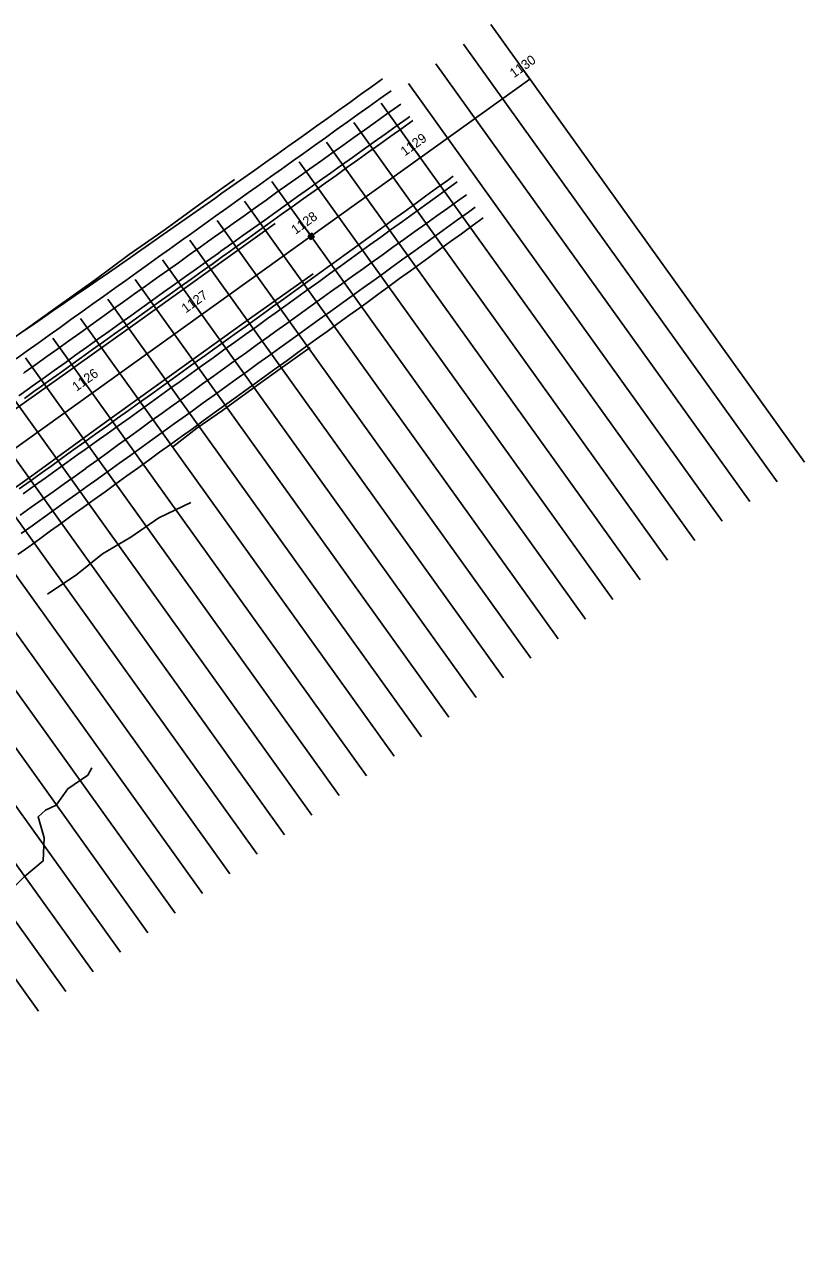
# Model space of a CAD drawing. Extents: x -354 to 8821, y -19535 to 19639.
# Drawn here: x 8242 to 8821, y 1707 to 2622 of the extents above; entities that cross this region are included whole.
import ezdxf

# ---------------------------------------------------------------- set-up
doc = ezdxf.new("R2010")
doc.units = 0
for name, color, linetype in [('DR_X_Cells', 7, 'Continuous'), ('GK_Drainage_Nodes', 7, 'Continuous'), ('PV_X_COP', 7, 'Continuous'), ('PV_X_EOP', 7, 'Continuous'), ('PV_X_Shoulder_Aggregate', 7, 'Continuous'), ('RW_X_CL_50', 7, 'Continuous'), ('SC_Scratch1', 7, 'Continuous'), ('SV_X_Edge_of_Slip', 7, 'Continuous'), ('SV_X_Top_of_Bank', 7, 'Continuous')]:
    doc.layers.add(name, color=color, linetype=linetype)

msp = doc.modelspace()

# ---------------------------------------------------------------- linework, layer by layer
at = {"layer": 'DR_X_Cells'}
for p, q in [((8453.29, 2464.24), (8453.48, 2465.1)), ((8453.9, 2463.28), (8454.43, 2465.71)), ((8454.69, 2463.16), (8455.2, 2465.5)), ((8455.65, 2463.77), (8455.81, 2464.55))]:
    msp.add_line(p, q, dxfattribs=at)
for points in [[(8452.23, 2464.92), (8455.04, 2466.72), (8456.84, 2463.92), (8454.03, 2462.12)], [(8452.95, 2464.76), (8454.88, 2466), (8456.12, 2464.07), (8454.19, 2462.84)], [(8453.15, 2464.72), (8454.84, 2465.8), (8455.92, 2464.12), (8454.23, 2463.04)]]:
    msp.add_lwpolyline(points, close=True, dxfattribs=at)
at = {"layer": 'GK_Drainage_Nodes'}
for p, q in [((8453.63, 2465.82), (8453.63, 2465.82)), ((8453.69, 2463.88), (8453.69, 2463.88)), ((8453.99, 2465.26), (8453.99, 2465.26)), ((8454.54, 2464.42), (8454.54, 2464.42)), ((8454.54, 2464.42), (8454.54, 2464.42)), ((8454.54, 2464.42), (8454.54, 2464.42)), ((8455.08, 2463.58), (8455.08, 2463.58)), ((8455.38, 2464.96), (8455.38, 2464.96)), ((8455.44, 2463.02), (8455.44, 2463.02))]:
    msp.add_line(p, q, dxfattribs=at)
at = {"layer": 'PV_X_COP'}
for points in [[(8240.75, 2362.63), (8241.93, 2363.47), (8250.06, 2369.29), (8258.19, 2375.11), (8266.33, 2380.93), (8274.46, 2386.74), (8282.6, 2392.56), (8290.73, 2398.37), (8298.87, 2404.19), (8307.01, 2410), (8315.14, 2415.81), (8323.28, 2421.63), (8331.42, 2427.44), (8339.56, 2433.25), (8347.69, 2439.06), (8355.83, 2444.87), (8363.97, 2450.68), (8372.11, 2456.49), (8380.25, 2462.3), (8388.39, 2468.11), (8396.53, 2473.91), (8404.67, 2479.72), (8412.82, 2485.53), (8420.96, 2491.33), (8429.1, 2497.14), (8437.24, 2502.94), (8445.39, 2508.75), (8453.53, 2514.55), (8461.67, 2520.35), (8469.82, 2526.16), (8477.96, 2531.96), (8486.11, 2537.76), (8494.26, 2543.56), (8502.4, 2549.36), (8510.55, 2555.16), (8518.69, 2560.96), (8521.05, 2562.63)], [(8246.57, 2263.13), (8254.71, 2268.94), (8262.85, 2274.75), (8270.99, 2280.56), (8279.13, 2286.37), (8287.1, 2292.05), (8287.1, 2292.05), (8287.11, 2292.06), (8287.13, 2292.08), (8287.15, 2292.09), (8287.17, 2292.1), (8287.17, 2292.1), (8295.26, 2297.97), (8303.36, 2303.83), (8311.46, 2309.7), (8319.57, 2315.56), (8327.67, 2321.42), (8335.77, 2327.28), (8343.88, 2333.13), (8351.99, 2338.99), (8357.68, 2343.1), (8365.79, 2348.95), (8373.9, 2354.8), (8382.01, 2360.65), (8390.13, 2366.5), (8398.24, 2372.34), (8406.36, 2378.18), (8414.47, 2384.02), (8422.59, 2389.86), (8428.29, 2393.96), (8436.42, 2399.8), (8444.54, 2405.63), (8452.66, 2411.46), (8460.78, 2417.3), (8468.91, 2423.12), (8477.04, 2428.95), (8485.17, 2434.78), (8493.3, 2440.6), (8499.01, 2444.69), (8507.14, 2450.51), (8515.27, 2456.33), (8523.41, 2462.14), (8531.54, 2467.96), (8539.68, 2473.77), (8547.82, 2479.58), (8555.96, 2485.39), (8564.1, 2491.2), (8569.82, 2495.28)], [(8238.44, 2257.32), (8246.57, 2263.13)]]:
    msp.add_lwpolyline(points, dxfattribs=at)
at = {"layer": 'PV_X_EOP'}
for points in [[(8513.88, 2572.53), (8505.74, 2566.73), (8497.6, 2560.92), (8489.46, 2555.11), (8481.32, 2549.3), (8473.18, 2543.49), (8465.04, 2537.68), (8456.9, 2531.87), (8448.76, 2526.06), (8440.62, 2520.25), (8432.48, 2514.44), (8424.35, 2508.63), (8416.21, 2502.82), (8408.07, 2497.01), (8399.93, 2491.19), (8391.8, 2485.38), (8383.66, 2479.57), (8375.53, 2473.75), (8373.69, 2472.44), (8365.56, 2466.63), (8357.42, 2460.81), (8349.29, 2455), (8341.15, 2449.18), (8333.02, 2443.37), (8324.88, 2437.55), (8316.75, 2431.73), (8308.62, 2425.91), (8300.48, 2420.09), (8292.35, 2414.28), (8284.22, 2408.46), (8276.08, 2402.64), (8267.95, 2396.82), (8259.82, 2391), (8251.69, 2385.18), (8243.56, 2379.35), (8235.43, 2373.53)], [(8237.26, 2345.92), (8245.39, 2351.74), (8247.28, 2353.09), (8255.41, 2358.91), (8263.54, 2364.73), (8271.67, 2370.55), (8279.8, 2376.37), (8287.94, 2382.19), (8296.07, 2388.01), (8304.2, 2393.82), (8312.34, 2399.64), (8320.47, 2405.46), (8328.61, 2411.27), (8336.74, 2417.09), (8344.88, 2422.9), (8353.01, 2428.72), (8361.15, 2434.53), (8369.28, 2440.35), (8377.42, 2446.16), (8385.56, 2451.97), (8387.45, 2453.32), (8395.59, 2459.14), (8403.72, 2464.95), (8411.86, 2470.76), (8420, 2476.57), (8428.14, 2482.38), (8436.28, 2488.19), (8444.42, 2494), (8452.56, 2499.81), (8460.7, 2505.62), (8468.84, 2511.43), (8476.98, 2517.23), (8485.12, 2523.04), (8493.26, 2528.85), (8501.4, 2534.65), (8509.55, 2540.46), (8517.69, 2546.26), (8525.83, 2552.07), (8527.72, 2553.42)], [(8562.88, 2504.86), (8554.77, 2499), (8546.67, 2493.15), (8538.56, 2487.29), (8530.46, 2481.43), (8522.35, 2475.58), (8514.24, 2469.73), (8506.13, 2463.87), (8498.02, 2458.02), (8492.56, 2454.08), (8484.45, 2448.23), (8476.34, 2442.38), (8468.22, 2436.54), (8460.11, 2430.69), (8452, 2424.84), (8443.88, 2419), (8435.77, 2413.16), (8427.65, 2407.32), (8422.18, 2403.38), (8414.06, 2397.54), (8405.94, 2391.7), (8397.82, 2385.87), (8389.7, 2380.03), (8381.58, 2374.2), (8373.46, 2368.36), (8365.34, 2362.53), (8357.21, 2356.7), (8351.74, 2352.77), (8343.61, 2346.94), (8335.49, 2341.11), (8327.36, 2335.29), (8319.23, 2329.46), (8311.11, 2323.64), (8302.98, 2317.81), (8294.85, 2311.99), (8286.72, 2306.17), (8281.24, 2302.25), (8281.24, 2302.25), (8273.1, 2296.43), (8264.97, 2290.61), (8256.84, 2284.79), (8248.71, 2278.97), (8240.58, 2273.15)], [(8239.06, 2243.6), (8247.19, 2249.42), (8255.33, 2255.24), (8263.46, 2261.07), (8271.59, 2266.89), (8279.72, 2272.71), (8287.85, 2278.53), (8295.98, 2284.35), (8296.14, 2284.47), (8296.14, 2284.47), (8296.14, 2284.47), (8296.15, 2284.48), (8296.16, 2284.48), (8296.17, 2284.49), (8296.17, 2284.49), (8304.29, 2290.32), (8312.41, 2296.16), (8320.53, 2301.99), (8328.65, 2307.83), (8336.77, 2313.67), (8344.89, 2319.5), (8353.01, 2325.34), (8361.13, 2331.18), (8366.26, 2334.86), (8374.38, 2340.7), (8382.5, 2346.54), (8390.62, 2352.38), (8398.74, 2358.22), (8406.85, 2364.05), (8414.97, 2369.89), (8423.09, 2375.73), (8431.21, 2381.57), (8436.34, 2385.26), (8444.45, 2391.1), (8452.57, 2396.94), (8460.69, 2402.79), (8468.8, 2408.63), (8476.92, 2414.47), (8485.03, 2420.31), (8493.15, 2426.15), (8501.27, 2432), (8506.39, 2435.69), (8514.51, 2441.53), (8522.62, 2447.38), (8530.74, 2453.22), (8538.85, 2459.06), (8546.97, 2464.91), (8555.08, 2470.75), (8563.19, 2476.6), (8571.31, 2482.45), (8576.43, 2486.14)]]:
    msp.add_lwpolyline(points, dxfattribs=at)
at = {"layer": 'PV_X_Shoulder_Aggregate'}
for points in [[(8507.45, 2581.41), (8499.34, 2575.57), (8491.22, 2569.73), (8483.1, 2563.89), (8474.98, 2558.06), (8466.85, 2552.24), (8458.71, 2546.42), (8450.57, 2540.61), (8445.31, 2536.86), (8437.17, 2531.06), (8429.02, 2525.27), (8420.86, 2519.48), (8412.7, 2513.7), (8404.54, 2507.92), (8396.37, 2502.15), (8388.2, 2496.39), (8382.92, 2492.67), (8374.74, 2486.92), (8366.56, 2481.17), (8358.37, 2475.43), (8350.18, 2469.69), (8341.98, 2463.97), (8333.78, 2458.24), (8325.58, 2452.53), (8320.28, 2448.84), (8312.07, 2443.13), (8303.85, 2437.43), (8295.63, 2431.74), (8287.4, 2426.05), (8279.18, 2420.37), (8270.94, 2414.69), (8262.7, 2409.02), (8257.38, 2405.36), (8257.38, 2405.36), (8249.15, 2399.69), (8240.92, 2394.01)], [(8529.9, 2550.41), (8521.76, 2544.6), (8513.63, 2538.78), (8505.49, 2532.97), (8497.35, 2527.16), (8489.22, 2521.34), (8481.08, 2515.53), (8472.95, 2509.71), (8464.81, 2503.89), (8456.68, 2498.08), (8448.54, 2492.26), (8440.41, 2486.45), (8432.27, 2480.63), (8424.14, 2474.81), (8416.01, 2468.99), (8407.87, 2463.17), (8399.74, 2457.36), (8391.61, 2451.54), (8389.72, 2450.18), (8381.59, 2444.36), (8373.45, 2438.54), (8365.32, 2432.72), (8357.19, 2426.9), (8349.06, 2421.08), (8340.93, 2415.26), (8332.8, 2409.44), (8324.67, 2403.62), (8316.54, 2397.8), (8308.41, 2391.97), (8300.28, 2386.15), (8292.15, 2380.33), (8284.02, 2374.5), (8275.89, 2368.68), (8267.76, 2362.85), (8259.63, 2357.03), (8251.5, 2351.2), (8249.61, 2349.85), (8241.48, 2344.02)], [(8213.46, 2374.92), (8242.12, 2395.08), (8264.83, 2411.31), (8293.95, 2432.25), (8319.36, 2450.9), (8346.08, 2469.45), (8371.91, 2488.23), (8397.55, 2506.71)], [(8245.76, 2282.64), (8253.89, 2288.47), (8262.01, 2294.3), (8270.14, 2300.13), (8278.26, 2305.96), (8286.38, 2311.79), (8294.51, 2317.62), (8302.63, 2323.45), (8310.76, 2329.28), (8318.88, 2335.12), (8327, 2340.95), (8335.12, 2346.78), (8343.25, 2352.61), (8351.37, 2358.45), (8359.49, 2364.28), (8367.61, 2370.11), (8375.74, 2375.95), (8381.12, 2379.82), (8381.12, 2379.82), (8389.24, 2385.65), (8397.36, 2391.49), (8405.48, 2397.33), (8413.59, 2403.17), (8421.71, 2409.02), (8425.88, 2412.02), (8433.99, 2417.87), (8442.1, 2423.72), (8450.21, 2429.57), (8458.31, 2435.42), (8466.42, 2441.28), (8470.58, 2444.29), (8478.69, 2450.15), (8486.79, 2456.01), (8494.89, 2461.88), (8502.99, 2467.74), (8511.08, 2473.61), (8515.24, 2476.63), (8523.34, 2482.5), (8531.43, 2488.38), (8539.52, 2494.25), (8547.61, 2500.13), (8555.7, 2506.01), (8559.85, 2509.04)], [(8582.18, 2478.19), (8574.11, 2472.29), (8566.04, 2466.4), (8557.96, 2460.5), (8549.88, 2454.61), (8541.8, 2448.71), (8536.39, 2444.78), (8528.31, 2438.89), (8520.23, 2433), (8512.14, 2427.12), (8504.05, 2421.24), (8495.97, 2415.36), (8490.55, 2411.43), (8482.46, 2405.55), (8474.37, 2399.68), (8466.27, 2393.81), (8458.18, 2387.94), (8450.08, 2382.07), (8444.66, 2378.15), (8436.56, 2372.29), (8428.46, 2366.42), (8420.35, 2360.57), (8412.25, 2354.71), (8404.14, 2348.85), (8398.72, 2344.94), (8382.5, 2333.24), (8374.39, 2327.39), (8366.28, 2321.54), (8358.17, 2315.68), (8350.06, 2309.83), (8341.95, 2303.98), (8333.84, 2298.13), (8325.73, 2292.28), (8317.62, 2286.43), (8309.51, 2280.58), (8301.4, 2274.73), (8293.29, 2268.88), (8285.18, 2263.04), (8277.07, 2257.19), (8268.96, 2251.34), (8260.98, 2245.59), (8252.87, 2239.74), (8244.76, 2233.89), (8236.65, 2228.05)], [(8427.82, 2473.88), (8377.92, 2438.43), (8325.47, 2400.65), (8273.79, 2363.79), (8221.55, 2326.85), (8180.8, 2297.81), (8128.12, 2260.38), (8082.15, 2226.78), (8028.58, 2188.39), (7978.98, 2152.72), (7933.92, 2120.35), (7882.32, 2083.22), (7833.79, 2048.53), (7785.45, 2013.27), (7732.67, 1975.86), (7693.88, 1947.56), (7645.37, 1913.17), (7595.97, 1878.05), (7566.01, 1856.18)], [(8455.97, 2436.7), (8404.42, 2400.06), (8350.84, 2361.5), (8300.75, 2325.62), (8248.8, 2287.69), (8207.76, 2258.6), (8155.02, 2221.78), (8108.79, 2189.02), (8054.7, 2149.69), (8004.91, 2114.31), (7957.66, 2080.83), (7908.19, 2045.16), (7859.18, 2009.79), (7810.29, 1974.92), (7758.63, 1937.48), (7720.6, 1910.02), (7671.27, 1875.01), (7622.48, 1839.57), (7594.92, 1820.15)], [(8453.66, 2381.8), (8431.58, 2366.1), (8408.75, 2349.75), (8388.67, 2335.05), (8369.65, 2322.03), (8351.78, 2308.14)], [(8237.64, 2276.81), (8245.76, 2282.64)]]:
    msp.add_lwpolyline(points, dxfattribs=at)
at = {"layer": 'RW_X_CL_50'}
for p, q in [((7397.71, 1707.37), (8616.98, 2581.09)), ((8616.98, 2581.09), (8614.07, 2585.16)), ((8535.69, 2522.84), (8532.78, 2526.91)), ((8454.41, 2464.6), (8451.5, 2468.66)), ((8373.13, 2406.35), (8370.21, 2410.41)), ((8291.84, 2348.1), (8288.93, 2352.16))]:
    msp.add_line(p, q, dxfattribs=at)
at = {"layer": 'SC_Scratch1'}
for p, q in [((8587.85, 2621.73), (8820.85, 2296.6)), ((8567.53, 2607.17), (8800.53, 2282.04)), ((8547.21, 2592.61), (8780.21, 2267.47)), ((8526.89, 2578.05), (8759.88, 2252.91)), ((8506.57, 2563.49), (8739.56, 2238.35)), ((8486.25, 2548.92), (8719.24, 2223.79)), ((8465.93, 2534.36), (8698.92, 2209.22)), ((8445.61, 2519.8), (8678.6, 2194.66)), ((8425.29, 2505.24), (8658.28, 2180.1)), ((8404.96, 2490.68), (8637.96, 2165.54)), ((8384.64, 2476.11), (8617.64, 2150.98)), ((8364.32, 2461.55), (8597.32, 2136.41)), ((8344, 2446.99), (8576.99, 2121.85)), ((8323.68, 2432.43), (8556.67, 2107.29)), ((8303.36, 2417.87), (8536.35, 2092.73)), ((8283.04, 2403.3), (8516.03, 2078.17)), ((8262.72, 2388.74), (8495.71, 2063.6)), ((8242.4, 2374.18), (8475.39, 2049.04)), ((8222.07, 2359.62), (8455.07, 2034.48)), ((8201.75, 2345.05), (8434.75, 2019.92)), ((8181.43, 2330.49), (8414.43, 2005.36)), ((8161.11, 2315.93), (8394.1, 1990.79)), ((8140.79, 2301.37), (8373.78, 1976.23)), ((8120.47, 2286.81), (8353.46, 1961.67)), ((8100.15, 2272.24), (8333.14, 1947.11)), ((8079.83, 2257.68), (8312.82, 1932.55)), ((8059.51, 2243.12), (8292.5, 1917.98)), ((8039.19, 2228.56), (8272.18, 1903.42)), ((8018.86, 2214), (8251.86, 1888.86))]:
    msp.add_line(p, q, dxfattribs=at)
at = {"layer": 'SV_X_Edge_of_Slip'}
msp.add_lwpolyline([(8054.88, 1873.04), (8069.61, 1869.32), (8089.12, 1869.92), (8099.48, 1885.88), (8111.97, 1891.88), (8126.81, 1895.53), (8141.26, 1907.27), (8158.36, 1918.78), (8172.35, 1929.65), (8185.82, 1940.62), (8194.87, 1949.12), (8202.21, 1950.26), (8211.45, 1956.29), (8219.75, 1964.62), (8227.26, 1974.29), (8241.45, 1988.96), (8255.42, 2000.41), (8256.25, 2017.66), (8251.64, 2033.1), (8257.06, 2038.08), (8265.09, 2041.93), (8273.75, 2054.01), (8288.57, 2064.01), (8291.7, 2069.53)], dxfattribs=at)
at = {"layer": 'SV_X_Top_of_Bank'}
msp.add_lwpolyline([(8258.66, 2198.67), (8280.36, 2213.32), (8299.53, 2228.5), (8320.53, 2240.93), (8341.25, 2255.28), (8365.06, 2266.64)], dxfattribs=at)

# ---------------------------------------------------------------- texts
at = {"layer": 'RW_X_CL_50'}
for s, p in [('1130', (8605.15, 2581.85)), ('1129', (8524.07, 2523.74)), ('1128', (8442.88, 2465.56)), ('1127', (8361.35, 2407.13)), ('1126', (8280.17, 2348.96))]:
    msp.add_text(s, height=7, rotation=35.62538, dxfattribs=at).set_placement(p)

doc.saveas('drawing.dxf')
